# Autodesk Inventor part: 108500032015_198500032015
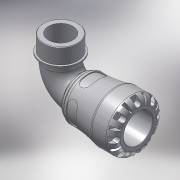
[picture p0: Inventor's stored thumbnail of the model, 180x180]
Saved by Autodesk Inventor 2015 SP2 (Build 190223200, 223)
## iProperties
Created: 2016-12
Part Number: 108500032015_198500032015
Material: PVC-Piping
Description: PLASSON 90° ELBOW WITH THREADED MALE OFFTAKE 32X1 1/2" SERIES 2
Document SubType Name: Modeling
Designer: KIM
Mass: 182.096 g
Surface Area: 391.421 cm^2
Volume: 130.069 cm^3
Density: 1.4 g/cm^3
Appearance: Smooth - White
Author: KIM
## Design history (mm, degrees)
derived "1085.ipt"
feature "Solid1::1085.ipt"
tag "TaggingFeature1"
body "Solid1"
other parameters: "d1" = 22.26, "d2" = 32, "d4" = 58, "d8" = 49.3, "d13" = 7.2, "d14" = 7.2, "d15" = 0, "d17" = 360 deg, "d19" = 8 deg, "d20" = 0.64, "d21" = 0.64, "d22" = 8 deg, "d24" = 0, "d26" = 360 deg, "d33" = 5.8, "d43" = 45.24, "d51" = 0.58, "d54" = 11.2, "d55" = 7.04, "d57" = 14.112, "d58" = 0, "d74" = 0, "d78" = 53, "d82" = 0.64, "d115" = 360 deg, "d207" = 90 deg, "d228" = 9.52, "d247" = 1.16, "d248" = 3.18, "d268" = 27.115, "d269" = 3.18, "d270" = 81, "d276" = 47.803, "d277" = 22, "d278" = 52.5833, "d279" = 62, "d280" = 24.2, "d281" = 7.17045, "d283" = 43.0227, "d286" = 0, "d287" = 0, "d288" = 33.4621, "d290" = 1.10865, "d292" = 30 deg, "d_" = 32, "E_" = 58, "l_" = 53, "A_" = 81, "A_1" = 62, "l_2" = 22, "R_" = 47.803, "d9" = 9, "d11" = 58, "d289" = 33.4621
